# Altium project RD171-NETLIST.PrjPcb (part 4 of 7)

## Sheet 5.SchDoc
size 420 x 297 mm
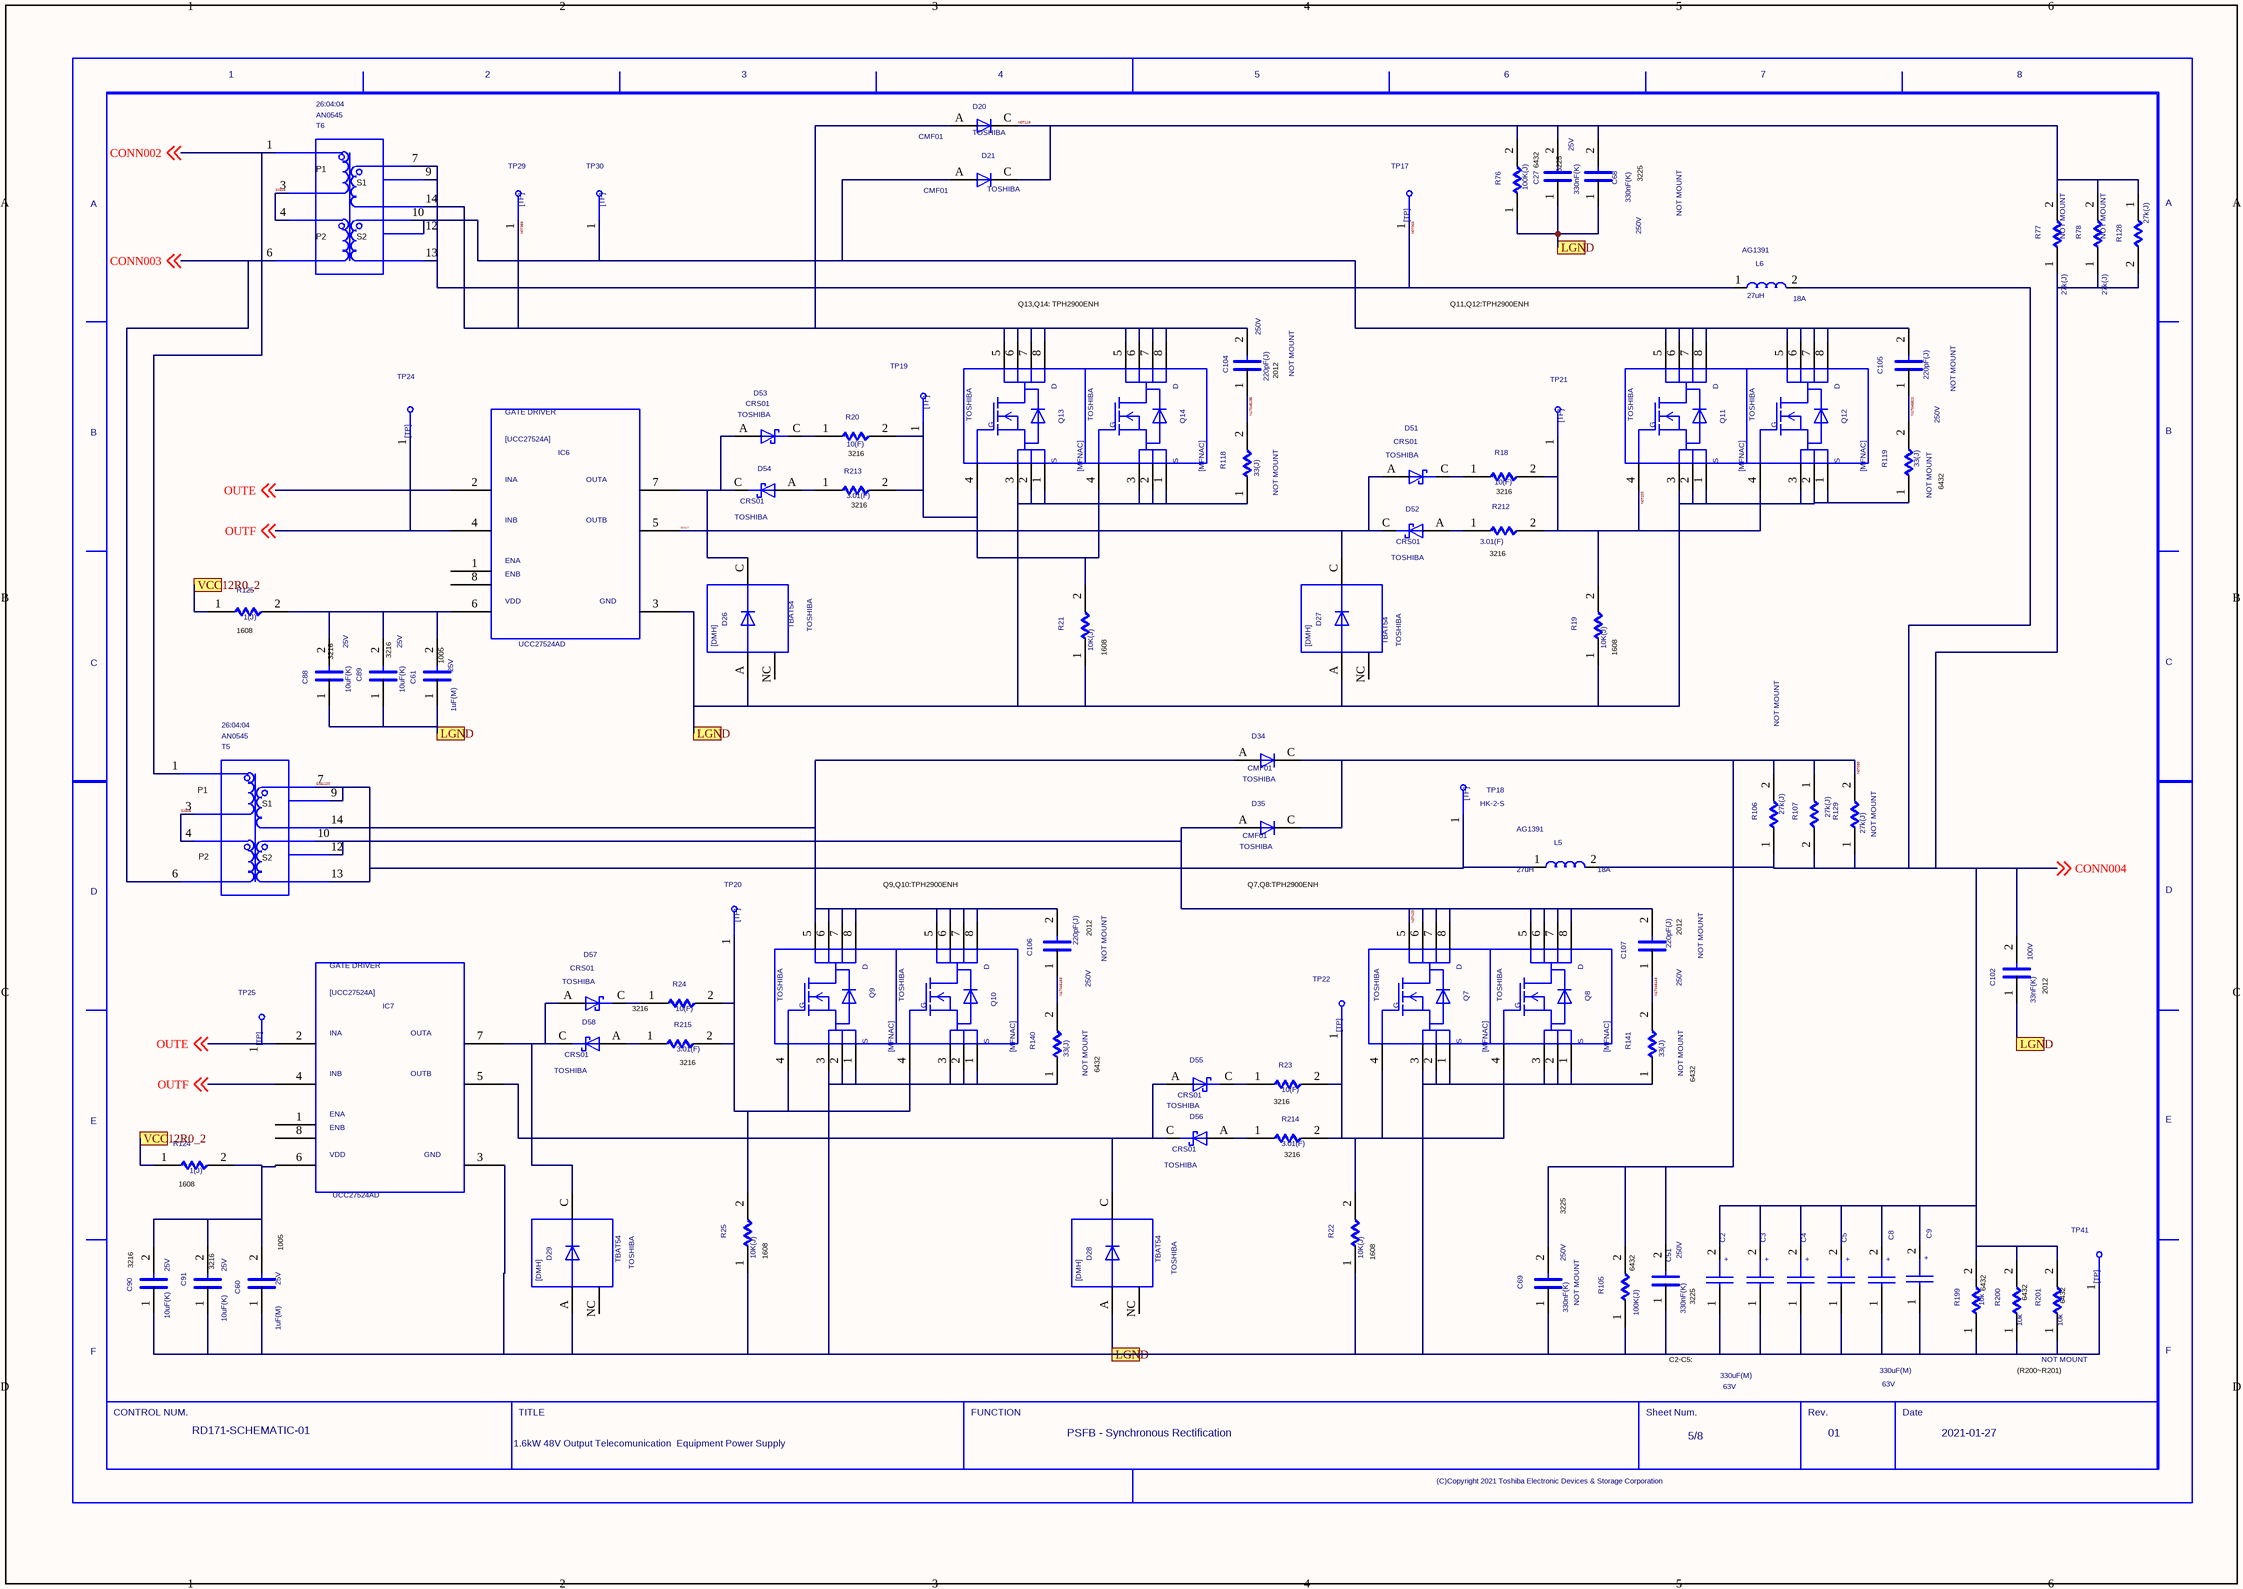
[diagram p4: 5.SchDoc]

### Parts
(Parts that share a designator on the sheet are numbered #1, #2 ... from top to bottom, then left to right.)
C2  VAL2: 63V  VAL1: 330uF(M)  [EKZN630ELL331MJ25S]  (hidden comment: 330uF)
C3  330uF  [EKZN630ELL331MJ25S]  (value not drawn)
C4  330uF  [EKZN630ELL331MJ25S]  (value not drawn)
C5  330uF  [EKZN630ELL331MJ25S]  (value not drawn)
C8  VAL2: 63V  VAL1: 330uF(M)  [EKZN630ELL331MJ25S]  (hidden comment: 330uF)
C9  330uF  [EKZN630ELL331MJ25S]  (value not drawn)
C27  VAL2: 25V  VAL1: 330nF(K)  [C3225X7T2E334K200AE]  (hidden comment: 330nF)
C51  VAL2: 250V  VAL1: 330nF(K)  [C3225X7T2E334K200AE]  (hidden comment: 330nF)
C60  VAL2: 25V  VAL1: 1uF(M)  (hidden comment: 1uF)
C61  VAL2: 25V  VAL1: 1uF(M)  (hidden comment: 1uF)
C68  MOUNT: NOT MOUNT  VAL2: 250V  VAL1: 330nF(K)  [C3225X7T2E334K200AE]  (hidden comment: 330nF)
C69  MOUNT: NOT MOUNT  VAL2: 250V  VAL1: 330nF(K)  [C3225X7T2E334K200AE]  (hidden comment: 330nF)
C88  VAL2: 25V  VAL1: 10uF(K)  (hidden comment: 10uF)
C89  VAL2: 25V  VAL1: 10uF(K)  (hidden comment: 10uF)
C90  VAL2: 25V  VAL1: 10uF(K)  (hidden comment: 10uF)
C91  VAL2: 25V  VAL1: 10uF(K)  (hidden comment: 10uF)
C102  VAL2: 100V  VAL1: 33nF(K)  [C2012C0G2A333J125AE]  (hidden comment: 33nF)
C104  MOUNT: NOT MOUNT  VAL2: 250V  VAL1: 220pF(J)  [GRM21A5C221J]  (hidden comment: 220pF)
C105  MOUNT: NOT MOUNT  VAL2: 250V  VAL1: 220pF(J)  [GRM21A5C221J]  (hidden comment: 220pF)
C106  MOUNT: NOT MOUNT  VAL2: 250V  VAL1: 220pF(J)  [GRM21A5C221J]  (hidden comment: 220pF)
C107  MOUNT: NOT MOUNT  VAL2: 250V  VAL1: 220pF(J)  [GRM21A5C221J]  (hidden comment: 220pF)
D20  USERCOMPTEXT3: TOSHIBA  [CMF01]  (hidden comment: D20)
D21  USERCOMPTEXT3: TOSHIBA  [CMF01]  (hidden comment: D21)
D26  USERCOMPTEXT3: TOSHIBA  [TBAT54]  (hidden comment: D26)
D27  USERCOMPTEXT3: TOSHIBA  [TBAT54]  (hidden comment: D27)
D28  USERCOMPTEXT3: TOSHIBA  [TBAT54]  (hidden comment: D28)
D29  USERCOMPTEXT3: TOSHIBA  [TBAT54]  (hidden comment: D29)
D34  USERCOMPTEXT3: TOSHIBA  [CMF01]  (hidden comment: D34)
D35  USERCOMPTEXT3: TOSHIBA  [CMF01]  (hidden comment: D35)
D51  USERCOMPTEXT3: TOSHIBA  [CRS01]  (hidden comment: D51)
D52  USERCOMPTEXT3: TOSHIBA  [CRS01]  (hidden comment: D52)
D53  USERCOMPTEXT3: TOSHIBA  [CRS01]  (hidden comment: D53)
D54  USERCOMPTEXT3: TOSHIBA  [CRS01]  (hidden comment: D54)
D55  USERCOMPTEXT3: TOSHIBA  [CRS01]  (hidden comment: D55)
D56  USERCOMPTEXT3: TOSHIBA  [CRS01]  (hidden comment: D56)
D57  USERCOMPTEXT3: TOSHIBA  [CRS01]  (hidden comment: D57)
D58  USERCOMPTEXT3: TOSHIBA  [CRS01]  (hidden comment: D58)
IC6  IC6  [UCC27524AD]  (value not drawn)
IC7  IC7  [UCC27524AD]  (value not drawn)
L5  VAL3: AG1391  VAL2: 18A  [AG-1391]  (hidden comment: 27uH)
L6  VAL3: AG1391  VAL2: 18A  [AG-1391]  (hidden comment: 27uH)
Q7  USERCOMPTEXT3: TOSHIBA  [TPH2900ENH]  (hidden comment: Q7)
Q8  USERCOMPTEXT3: TOSHIBA  [TPH2900ENH]  (hidden comment: Q8)
Q9  USERCOMPTEXT3: TOSHIBA  [TPH2900ENH]  (hidden comment: Q9)
Q10  USERCOMPTEXT3: TOSHIBA  [TPH2900ENH]  (hidden comment: Q10)
Q11  USERCOMPTEXT3: TOSHIBA  [TPH2900ENH]  (hidden comment: Q11)
Q12  USERCOMPTEXT3: TOSHIBA  [TPH2900ENH]  (hidden comment: Q12)
Q13  USERCOMPTEXT3: TOSHIBA  [TPH2900ENH]  (hidden comment: Q13)
Q14  USERCOMPTEXT3: TOSHIBA  [TPH2900ENH]  (hidden comment: Q14)
R18  VAL1: 10(F)  (hidden comment: 10)
R19  VAL1: 10K(J)  (hidden comment: 10k)
R20  VAL1: 10(F)  (hidden comment: 10)
R21  VAL1: 10K(J)  (hidden comment: 10k)
R22  VAL1: 10K(J)  (hidden comment: 10k)
R23  VAL1: 10(F)  (hidden comment: 10)
R24  VAL1: 10(F)  (hidden comment: 10)
R25  VAL1: 10K(J)  (hidden comment: 10k)
R76  VAL1: 100K(J)  [RK73B3ATTE104J]  (hidden comment: 100k)
R77  VAL2: NOT MOUNT  VAL1: 27k(J)  [MOS3CT631R273J]  (hidden comment: R)
R78  VAL2: NOT MOUNT  VAL1: 27k(J)  [MOS3CT631R273J]  (hidden comment: 27k)
R105  VAL1: 100K(J)  [RK73B3ATTE104J]  (hidden comment: 100k)
R106  VAL2: NOT MOUNT  VAL1: 27k(J)  [MOS3CT631R273J]  (hidden comment: 27k)
R107  VAL1: 27k(J)  [MOS3CT631R273J]  (hidden comment: 27k)
R118  VAL1: 33(J)  MOUNT: NOT MOUNT  [RK73B3ATTE330J]  (hidden comment: 33)
R119  VAL1: 33(J)  MOUNT: NOT MOUNT  [RK73B3ATTE330J]  (hidden comment: 33)
R124  VAL1: 1(J)  (hidden comment: 1)
R125  VAL1: 1(J)  (hidden comment: 1)
R128  VAL1: 27k(J)  [MOS3CT631R273J]  (hidden comment: 27k)
R129  VAL2: NOT MOUNT  VAL1: 27k(J)  [MOS3CT631R273J]  (hidden comment: 27k)
R140  VAL1: 33(J)  MOUNT: NOT MOUNT  [RK73B3ATTE330J]  (hidden comment: 33)
R141  VAL1: 33(J)  MOUNT: NOT MOUNT  [RK73B3ATTE330J]  (hidden comment: 33)
R199  10k  [RK73B3ATTE104J]
R200  NOTMOUNT: NOT MOUNT  [RK73B3ATTE104J]  (hidden comment: 10k)
R201  10k  [RK73B3ATTE104J]
R212  VAL1: 3.01(F)  (hidden comment: 3.01)
R213  VAL1: 3.01(F)  (hidden comment: 3.01)
R214  VAL1: 3.01(F)  (hidden comment: 3.01)
R215  VAL1: 3.01(F)  (hidden comment: 3.01)
T5  VAL1: 26:04:04  VAL3: AN0545  (hidden comment: T3_12V67A)
T6  VAL1: 26:04:04  VAL3: AN0545  (hidden comment: T3_12V67A)
TP17  TP17  [HK-2-S]  (value not drawn)
TP18  TP18  [HK-2-S]  (value not drawn)
TP19  TP19  [HK-2-S]  (value not drawn)
TP20  TP20  [HK-2-S]  (value not drawn)
TP21  TP21  [HK-2-S]  (value not drawn)
TP22  TP22  [HK-2-S]  (value not drawn)
TP24  TP24  [HK-2-S]  (value not drawn)
TP25  TP25  [HK-2-S]  (value not drawn)
TP29  TP29  [HK-2-S]  (value not drawn)
TP30  TP30  [HK-2-S]  (value not drawn)
TP41  TP41  [LC-22-S-BLACK]  (value not drawn)
U?#5  DATE: 2021-01-27  REVISION: 01  SHEETNUMBER: 5/8  FUNCTION: PSFB - Synchronous Rectification  TITLE: 1.6kW 48V Output Telecomunication / Equipment Power Supply  DRAWINGNUMBER: RD171-SCHEMATIC-01  (hidden comment: WAKU_DEF100)

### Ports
LGND, VCC12R0_2

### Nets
CONN002: T5.1 T6.1 ; off-sheet CONN002
CONN003: T5.6 T6.6 ; off-sheet CONN003
CONN004: C2.2 C3.2 C4.2 C5.2 C8.2 C9.2 C102.2 L5.2 L6.2 R77.1 R78.1 R106.1 R107.2 R128.2 R129.1 R199.2 R200.2 R201.2 ; off-sheet CONN004
LGND: C2.1 C3.1 C4.1 C5.1 C8.1 C9.1 C27.1 C51.1 C60.1 C61.1 C68.1 C69.1 C88.1 C89.1 C90.1 C91.1 C102.1 D26.A D27.A D28.A D29.A IC6.3 IC7.3 Q7.1 Q7.2 Q7.3 Q8.1 Q8.2 Q8.3 Q9.1 Q9.2 Q9.3 Q10.1 Q10.2 Q10.3 Q11.1 Q11.2 Q11.3 Q12.1 Q12.2 Q12.3 Q13.1 Q13.2 Q13.3 Q14.1 Q14.2 Q14.3 R19.1 R21.1 R22.1 R25.1 R76.1 R105.1 R118.1 R119.1 R140.1 R141.1 R199.1 R200.1 R201.1 TP41.1 ; port LGND
N07003: L6.1 T6.7 T6.9 T6.13 TP17.1
N07083: C51.2 C69.2 D34.C D35.C R105.2 R106.2 R107.1 R129.2
N07119: C27.2 C68.2 D20.C D21.C R76.2 R77.2 R78.2 R128.1
N07203: Q11.4 Q12.4 R18.2 R19.2 R212.2 TP21.1
N07369: C104.2 D20.A Q13.5 Q13.6 Q13.7 Q13.8 Q14.5 Q14.6 Q14.7 Q14.8 T6.14 TP29.1
N07429: C107.2 D35.A Q7.5 Q7.6 Q7.7 Q7.8 Q8.5 Q8.6 Q8.7 Q8.8 T5.10 T5.12
N17045135: C104.1 R118.2
N17045143: C107.1 R141.2
N17045153: C106.1 R140.2
N17045822: C105.1 R119.2
OUTE: IC6.2 IC7.2 TP25.1 ; off-sheet OUTE
OUTF: IC6.4 IC7.4 TP24.1 ; off-sheet OUTF
SIG14: T6.3 T6.4
SIG16: T5.3 T5.4
SIG115: C106.2 D34.A Q9.5 Q9.6 Q9.7 Q9.8 Q10.5 Q10.6 Q10.7 Q10.8 T5.14
SIG116: D29.C D57.A D58.C IC7.7
SIG117: D28.C D55.A D56.C IC7.5
SIG118: Q9.4 Q10.4 R24.2 R25.2 R215.2 TP20.1
SIG121: C60.2 C90.2 C91.2 IC7.6 R124.2
SIG124: C61.2 C88.2 C89.2 IC6.6 R125.2
SIG126: D26.C D53.A D54.C IC6.7
SIG127: D27.C D51.A D52.C IC6.5
SIG128: Q13.4 Q14.4 R20.2 R21.2 R213.2 TP19.1
SIG135: C105.2 D21.A Q11.5 Q11.6 Q11.7 Q11.8 Q12.5 Q12.6 Q12.7 Q12.8 T6.10 T6.12 TP30.1
SIG1120: L5.1 T5.7 T5.9 T5.13 TP18.1
SIGN336: D53.C R20.1
SIGN337: D54.A R213.1
SIGN338: D51.C R18.1
SIGN339: D52.A R212.1
SIGN341: D57.C R24.1
SIGN342: D58.A R215.1
SIGN343: Q7.4 Q8.4 R22.2 R23.2 R214.2 TP22.1
SIGN344: D55.C R23.1
SIGN345: D56.A R214.1
NetC809_2: R124.1 R125.1 ; port VCC12R0_2

Not connected (* = marked no-connect by the designer): D26 NC; D27 NC; D28 NC; D29 NC; IC6 1 8; IC7 1 8

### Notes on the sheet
- (near T6) P1
- (near T6) S1
- 6432
- (near C27) 3225
- (near C68) 3225
- (near T6) P2
- (near T6) S2
- Q13,Q14: TPH2900ENH
- Q11,Q12:TPH2900ENH
- (near C104) 2012
- (near R20) 3216
- (near R213) 3216
- (near R18) 3216
- (near R119) 6432
- (near R212) 3216
- (near R125) 1608
- (near C88) 3216
- (near C89) 3216
- (near C61) 1005
- (near R21) 1608
- (near R19) 1608
- (near T5) P1
- (near T5) P2
- (near T5) S2
- (near T5) S1
- Q9,Q10:TPH2900ENH
- (near C106) 2012
- Q7,Q8:TPH2900ENH
- (near C107) 2012
- (near C102) 2012
- 3216
- (near R215) 3216
- (near R140) 6432
- (near R23) 3216
- (near R141) 6432
- (near R124) 1608
- (near R214) 3216
- (near C90) 3216
- (near C91) 3216
- (near C60) 1005
- (near R25) 1608
- (near R22) 1608
- 3225
- (near R105) 6432
- (near R199) 6432
- (near R200) 6432
- (near R201) 6432
- C2-C5:
- (R200~R201)

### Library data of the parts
C2 = CP: PARTNAME: EKZN630ELL331MJ25S_CC; OUMEPARTTYPE: C; UPDATEUSER: t5459927; UPDATETIME: 16:40:04; SAVECOUNT: 1; SAVEAREA0: -1450,-153,20294,13055; ORIGINALSYMBOLORIGIN: (0,0); QUADMODEL: CON_56U; FUNCTION: CP_CP.Normal_package; NOMINALCAPACITA: 56u; RATEDVOLTAGE: 16; CDMASTERCADCELG: DC0341; MAKER: RUBYCON; SIZECODESMD: DIP; COMP: PRT_3; PMPRODUCTSTYPEG: SV1; FNLEADFREETHET1GT2GMCTH1: 0_2_N; CAPACITANCETOLE: M; OUMECLASSIFICATION: アルミ電解コンデンサ; CHIPSIZE: D10xL22; INSTANCENAME: INS5781
C3 = CP: PARTNAME: EKZN630ELL331MJ25S_CC; UPDATEUSER: t5459927; UPDATETIME: 16:40:04; SAVECOUNT: 1; SAVEAREA0: -1450,-153,20294,13055; ORIGINALSYMBOLORIGIN: (0,0); FUNCTION: CP_CP.Normal_package; NOMINALCAPACITA: 56u; RATEDVOLTAGE: 16; MAKER: RUBYCON; SIZECODESMD: DIP; COMP: PRT_3; PMPRODUCTSTYPEG: SV1; VAL3: 25ZLQ1500MEFC10X25; VAL2: 63V; CAPACITANCETOLE: M; VAL1: 330uF(M); CHIPSIZE: D10xL22; INSTANCENAME: INS5793
C4 = CP: PARTNAME: EKZN630ELL331MJ25S_CC; UPDATEUSER: t5459927; UPDATETIME: 16:40:04; SAVECOUNT: 1; SAVEAREA0: -1450,-153,20294,13055; ORIGINALSYMBOLORIGIN: (0,0); FUNCTION: CP_CP.Normal_package; NOMINALCAPACITA: 56u; RATEDVOLTAGE: 16; MAKER: RUBYCON; SIZECODESMD: DIP; COMP: PRT_3; PMPRODUCTSTYPEG: SV1; VAL3: 25ZLQ1500MEFC10X25; VAL2: 63V; CAPACITANCETOLE: M; VAL1: 330uF(M); CHIPSIZE: D10xL22; INSTANCENAME: INS5801
C5 = CP: PARTNAME: EKZN630ELL331MJ25S_CC; UPDATEUSER: t5459927; UPDATETIME: 16:40:04; SAVECOUNT: 1; SAVEAREA0: -1450,-153,20294,13055; ORIGINALSYMBOLORIGIN: (0,0); FUNCTION: CP_CP.Normal_package; NOMINALCAPACITA: 56u; RATEDVOLTAGE: 16; MAKER: RUBYCON; SIZECODESMD: DIP; COMP: PRT_3; PMPRODUCTSTYPEG: SV1; VAL3: 25ZLQ1500MEFC10X25; VAL2: 63V; CAPACITANCETOLE: M; VAL1: 330uF(M); CHIPSIZE: D10xL22; INSTANCENAME: INS5809
C8 = CP: PARTNAME: EKZN630ELL331MJ25S_CC; UPDATEUSER: t5459927; UPDATETIME: 16:40:04; SAVECOUNT: 1; SAVEAREA0: -1450,-153,20294,13055; ORIGINALSYMBOLORIGIN: (0,0); FUNCTION: CP_CP.Normal_package; NOMINALCAPACITA: 56u; RATEDVOLTAGE: 16; MAKER: RUBYCON; SIZECODESMD: DIP; COMP: PRT_3; PMPRODUCTSTYPEG: SV1; VAL3: EKZN630ELL331M; CAPACITANCETOLE: M; CHIPSIZE: D10xL22; INSTANCENAME: INS17034209
C9 = CP: PARTNAME: EKZN630ELL331MJ25S_CC; UPDATEUSER: t5459927; UPDATETIME: 16:40:04; SAVECOUNT: 1; SAVEAREA0: -1450,-153,20294,13055; ORIGINALSYMBOLORIGIN: (0,0); FUNCTION: CP_CP.Normal_package; NOMINALCAPACITA: 56u; RATEDVOLTAGE: 16; MAKER: RUBYCON; SIZECODESMD: DIP; COMP: PRT_3; PMPRODUCTSTYPEG: SV1; VAL3: EKZN630ELL331M; VAL2: 63V; CAPACITANCETOLE: M; VAL1: 330uF(M); CHIPSIZE: D10xL22; INSTANCENAME: INS17035630
C27 = C: PARTNAME: Chip3225_GS_1; ORIGINALSYMBOLORIGIN: (0,0); TIME: 16:40:04; UPDATEUSER: t5459927; SAVECOUNT: 1; QUADMODEL: CON_220N; FUNCTION: C_C.Normal_package; NOMINALCAPACITA: 220n; RATEDVOLTAGE: 16; CDMASTERCADCELG: KC0005; MAKER: TDK; TEMPCHARACTERI2: B; SIZECODESMD: 1005; OUMEMAKER: TDK ＴＤＫ; COMP: PRT_52; ADSMODELNAME: s_C1005JB1C224KT; FNLEADFREETHET1GT2GMCTH1: N_N_N; VAL3: C1005X5R1E224K050BC; CAPACITANCETOLE: K; OUMECLASSIFICATION: セラミックコンデンサ; OUMEMAKERKATAMEI: C1005JB1C224KT; INSTANCENAME: INS6475
C51 = C: PARTNAME: Chip3225_GS_1; ORIGINALSYMBOLORIGIN: (0,0); TIME: 16:40:04; UPDATEUSER: t5459927; SAVECOUNT: 1; QUADMODEL: CON_220N; FUNCTION: C_C.Normal_package; NOMINALCAPACITA: 220n; RATEDVOLTAGE: 16; CDMASTERCADCELG: KC0005; MAKER: TDK; TEMPCHARACTERI2: B; SIZECODESMD: 3225; OUMEMAKER: TDK ＴＤＫ; COMP: PRT_52; ADSMODELNAME: s_C1005JB1C224KT; FNLEADFREETHET1GT2GMCTH1: N_N_N; CAPACITANCETOLE: K; OUMECLASSIFICATION: セラミックコンデンサ; CHIPSIZE: 1005; INSTANCENAME: INS17062697
C60 = C: PARTNAME: Chip1005_GS_2; ORIGINALSYMBOLORIGIN: (0,0); TIME: 16:40:04; UPDATEUSER: t5459927; SAVECOUNT: 1; QUADMODEL: CON_1U; FUNCTION: C_C.Normal_package; NOMINALCAPACITA: 1u; RATEDVOLTAGE: 25; CDMASTERCADCELG: KC0005; MAKER: TDK; TEMPCHARACTERI2: B; SIZECODESMD: 1005; OUMEMAKER: MRT 村田製作所; COMP: PRT_52; ADSMODELNAME: s_GRM155B31E105KA12D; PMPRODUCTSTYPEG: HD1; FNLEADFREETHET1GT2GMCTH1: 3_0_N; VAL3: C1005X5R1E105M050BC; CAPACITANCETOLE: K; OUMECLASSIFICATION: セラミックコンデンサ; OUMEMAKERKATAMEI: GRM155B31E105KA12D; INSTANCENAME: INS6615
C61 = C: PARTNAME: Chip1005_GS_2; ORIGINALSYMBOLORIGIN: (0,0); TIME: 16:40:04; UPDATEUSER: t5459927; SAVECOUNT: 1; QUADMODEL: CON_1U; FUNCTION: C_C.Normal_package; NOMINALCAPACITA: 1u; RATEDVOLTAGE: 25; CDMASTERCADCELG: KC0005; MAKER: TDK; TEMPCHARACTERI2: B; SIZECODESMD: 1005; OUMEMAKER: MRT 村田製作所; COMP: PRT_52; ADSMODELNAME: s_GRM155B31E105KA12D; PMPRODUCTSTYPEG: HD1; FNLEADFREETHET1GT2GMCTH1: 3_0_N; VAL3: C1005X5R1E105M050BC; CAPACITANCETOLE: K; OUMECLASSIFICATION: セラミックコンデンサ; OUMEMAKERKATAMEI: GRM155B31E105KA12D; INSTANCENAME: INS6565
C68 = C: PARTNAME: Chip3225_GS_1; ORIGINALSYMBOLORIGIN: (0,0); TIME: 16:40:04; UPDATEUSER: t5459927; SAVECOUNT: 1; NOTMOUNT: NOT MOUNT; QUADMODEL: CON_220N; FUNCTION: C_C.Normal_package; NOMINALCAPACITA: 220n; RATEDVOLTAGE: 16; CDMASTERCADCELG: KC0005; MAKER: TDK; TEMPCHARACTERI2: B; SIZECODESMD: 3225; OUMEMAKER: TDK ＴＤＫ; COMP: PRT_52; ADSMODELNAME: s_C1005JB1C224KT; FNLEADFREETHET1GT2GMCTH1: N_N_N; CAPACITANCETOLE: K; OUMECLASSIFICATION: セラミックコンデンサ; CHIPSIZE: 1005; INSTANCENAME: INS17036811
C69 = C: PARTNAME: Chip3225_GS_1; ORIGINALSYMBOLORIGIN: (0,0); TIME: 16:40:04; UPDATEUSER: t5459927; SAVECOUNT: 1; NOTMOUNT: NOT MOUNT; QUADMODEL: CON_220N; FUNCTION: C_C.Normal_package; NOMINALCAPACITA: 220n; RATEDVOLTAGE: 16; CDMASTERCADCELG: KC0005; MAKER: TDK; TEMPCHARACTERI2: B; SIZECODESMD: 3225; OUMEMAKER: TDK ＴＤＫ; COMP: PRT_52; ADSMODELNAME: s_C1005JB1C224KT; FNLEADFREETHET1GT2GMCTH1: N_N_N; CAPACITANCETOLE: K; OUMECLASSIFICATION: セラミックコンデンサ; CHIPSIZE: 1005; INSTANCENAME: INS17039422
C88 = C: PARTNAME: Chip3216_GS_1; ORIGINALSYMBOLORIGIN: (0,0); TIME: 16:40:04; UPDATEUSER: t5459927; SAVECOUNT: 1; QUADMODEL: CON_10U; FUNCTION: C_C.Normal_package; NOMINALCAPACITA: 10u; RATEDVOLTAGE: 25; CDMASTERCADCELG: KC0014; MAKER: TAIYO YUDEN; SIZECODESMD: 3216; OUMEMAKER: TYD 太陽誘電; COMP: PRT_46; ADSMODELNAME: s_TMK316LD106KL_T; FNLEADFREETHET1GT2GMCTH1: N_N_N; VAL3: TMK316BJ106KL-T; CAPACITANCETOLE: K; OUMECLASSIFICATION: セラミックコンデンサ; OUMEMAKERKATAMEI: TMK316LD106KL-T; INSTANCENAME: INS6555
C89 = C: PARTNAME: Chip3216_GS_1; ORIGINALSYMBOLORIGIN: (0,0); TIME: 16:40:04; UPDATEUSER: t5459927; SAVECOUNT: 1; QUADMODEL: CON_10U; FUNCTION: C_C.Normal_package; NOMINALCAPACITA: 10u; RATEDVOLTAGE: 25; CDMASTERCADCELG: KC0014; MAKER: TAIYO YUDEN; SIZECODESMD: 3216; OUMEMAKER: TYD 太陽誘電; COMP: PRT_46; ADSMODELNAME: s_TMK316LD106KL_T; FNLEADFREETHET1GT2GMCTH1: N_N_N; VAL3: TMK316BJ106KL-T; CAPACITANCETOLE: K; OUMECLASSIFICATION: セラミックコンデンサ; OUMEMAKERKATAMEI: TMK316LD106KL-T; INSTANCENAME: INS6545
C90 = C: PARTNAME: Chip3216_GS_1; ORIGINALSYMBOLORIGIN: (0,0); TIME: 16:40:04; UPDATEUSER: t5459927; SAVECOUNT: 1; QUADMODEL: CON_10U; FUNCTION: C_C.Normal_package; NOMINALCAPACITA: 10u; RATEDVOLTAGE: 25; CDMASTERCADCELG: KC0014; MAKER: TAIYO YUDEN; SIZECODESMD: 3216; OUMEMAKER: TYD 太陽誘電; COMP: PRT_46; ADSMODELNAME: s_TMK316LD106KL_T; FNLEADFREETHET1GT2GMCTH1: N_N_N; VAL3: TMK316BJ106KL-T; CAPACITANCETOLE: K; OUMECLASSIFICATION: セラミックコンデンサ; OUMEMAKERKATAMEI: TMK316LD106KL-T; INSTANCENAME: INS6595
C91 = C: PARTNAME: Chip3216_GS_1; ORIGINALSYMBOLORIGIN: (0,0); TIME: 16:40:04; UPDATEUSER: t5459927; SAVECOUNT: 1; QUADMODEL: CON_10U; FUNCTION: C_C.Normal_package; NOMINALCAPACITA: 10u; RATEDVOLTAGE: 25; CDMASTERCADCELG: KC0014; MAKER: TAIYO YUDEN; SIZECODESMD: 3216; OUMEMAKER: TYD 太陽誘電; COMP: PRT_46; ADSMODELNAME: s_TMK316LD106KL_T; FNLEADFREETHET1GT2GMCTH1: N_N_N; VAL3: TMK316BJ106KL-T; CAPACITANCETOLE: K; OUMECLASSIFICATION: セラミックコンデンサ; OUMEMAKERKATAMEI: TMK316LD106KL-T; INSTANCENAME: INS6605
C102 = C: PARTNAME: Chip2012_GS_1; ORIGINALSYMBOLORIGIN: (0,0); TIME: 16:40:04; UPDATEUSER: t5459927; SAVECOUNT: 1; QUADMODEL: CON_100N; FUNCTION: C_C.Normal_package; NOMINALCAPACITA: 100n; RATEDVOLTAGE: 25; CDMASTERCADCELG: KC0005; MAKER: TDK; SIZECODESMD: 1005; OUMEMAKER: MRT 村田製作所; COMP: PRT_52; ADSMODELNAME: s_GRM155R71E104KE14D; FNLEADFREETHET1GT2GMCTH1: N_N_N; CAPACITANCETOLE: K; OUMECLASSIFICATION: セラミックコンデンサ; OUMEMAKERKATAMEI: GRM155R71E104KE14D; INSTANCENAME: INS6675
C104 = C: PARTNAME: Chip2012_GS_1; ORIGINALSYMBOLORIGIN: (0,0); TIME: 16:40:04; UPDATEUSER: t5459927; SAVECOUNT: 1; NOTMOUNT: NOT MOUNT; QUADMODEL: CON_100N; FUNCTION: C_C.Normal_package; NOMINALCAPACITA: 100n; RATEDVOLTAGE: 250; CDMASTERCADCELG: KC0005; MAKER: MURATA; SIZECODESMD: 2012; OUMEMAKER: MRT 村田製作所; COMP: PRT_52; ADSMODELNAME: s_GRM155R71E104KE14D; FNLEADFREETHET1GT2GMCTH1: N_N_N; VAL3: GRM21A5C2E221J; CAPACITANCETOLE: K; OUMECLASSIFICATION: セラミックコンデンサ; OUMEMAKERKATAMEI: GRM21A5C2E221JW01D; INSTANCENAME: INS17040886
C105 = C: PARTNAME: Chip2012_GS_1; ORIGINALSYMBOLORIGIN: (0,0); TIME: 16:40:04; UPDATEUSER: t5459927; SAVECOUNT: 1; NOTMOUNT: NOT MOUNT; QUADMODEL: CON_100N; FUNCTION: C_C.Normal_package; NOMINALCAPACITA: 100n; RATEDVOLTAGE: 250; CDMASTERCADCELG: KC0005; MAKER: MURATA; SIZECODESMD: 2012; OUMEMAKER: MRT 村田製作所; COMP: PRT_52; ADSMODELNAME: s_GRM155R71E104KE14D; FNLEADFREETHET1GT2GMCTH1: N_N_N; VAL3: GRM21A5C2E221J; CAPACITANCETOLE: K; OUMECLASSIFICATION: セラミックコンデンサ; OUMEMAKERKATAMEI: GRM21A5C2E221JW01D; INSTANCENAME: INS17040900
C106 = C: PARTNAME: Chip2012_GS_1; ORIGINALSYMBOLORIGIN: (0,0); TIME: 16:40:04; UPDATEUSER: t5459927; SAVECOUNT: 1; NOTMOUNT: NOT MOUNT; QUADMODEL: CON_100N; FUNCTION: C_C.Normal_package; NOMINALCAPACITA: 100n; RATEDVOLTAGE: 250; CDMASTERCADCELG: KC0005; MAKER: MURATA; SIZECODESMD: 2012; OUMEMAKER: MRT 村田製作所; COMP: PRT_52; ADSMODELNAME: s_GRM155R71E104KE14D; FNLEADFREETHET1GT2GMCTH1: N_N_N; VAL3: GRM21A5C2E221J; CAPACITANCETOLE: K; OUMECLASSIFICATION: セラミックコンデンサ; OUMEMAKERKATAMEI: GRM21A5C2E221JW01D; INSTANCENAME: INS17040913
C107 = C: PARTNAME: Chip2012_GS_1; ORIGINALSYMBOLORIGIN: (0,0); TIME: 16:40:04; UPDATEUSER: t5459927; SAVECOUNT: 1; NOTMOUNT: NOT MOUNT; QUADMODEL: CON_100N; FUNCTION: C_C.Normal_package; NOMINALCAPACITA: 100n; RATEDVOLTAGE: 250; CDMASTERCADCELG: KC0005; MAKER: MURATA; SIZECODESMD: 2012; OUMEMAKER: MRT 村田製作所; COMP: PRT_52; ADSMODELNAME: s_GRM155R71E104KE14D; FNLEADFREETHET1GT2GMCTH1: N_N_N; VAL3: GRM21A5C2E221J; CAPACITANCETOLE: K; OUMECLASSIFICATION: セラミックコンデンサ; OUMEMAKERKATAMEI: GRM21A5C2E221JW01D; INSTANCENAME: INS17040926
D20 = D: PARTNAME: CMF01_TS_B; UPDATEUSER: t5459927; UPDATETIME: 16:40:05; SAVECOUNT: 1; SAVEAREA0: -225,-91,12804,7836; ORIGINALSYMBOLORIGIN: (0,0); FUNCTION: D_D.Normal_package; CDMASTERCADCELG: KD0125; FORWARDVOLTAGEM: 0; MAXAVERAGEFORWA: 4; OUMEMAKER: ONS オンセミコンダクター; MOUNTINGFORMSMD: SMD; COMP: PRT_14; REVERSECURRENT: 250u; ADSMODELNAME: s_MURS340T3G@@; PMPRODUCTSTYPEG: HEV; MAXREPETITIVEPE: 400; FNLEADFREETHET1GT2GMCTH1: N_N_N; OUMECLASSIFICATION: 一般整流素子; OUMEMAKERKATAMEI: MURS340T3G@@; PEAKFORWARDVOLT: 1.28; INSTANCENAME: INS5897
D21 = D: PARTNAME: CMF01_TS_B; UPDATEUSER: t5459927; UPDATETIME: 16:40:05; SAVECOUNT: 1; SAVEAREA0: -225,-91,12804,7836; ORIGINALSYMBOLORIGIN: (0,0); FUNCTION: D_D.Normal_package; CDMASTERCADCELG: KD0125; FORWARDVOLTAGEM: 0; MAXAVERAGEFORWA: 4; OUMEMAKER: ONS オンセミコンダクター; MOUNTINGFORMSMD: SMD; COMP: PRT_14; REVERSECURRENT: 250u; ADSMODELNAME: s_MURS340T3G@@; PMPRODUCTSTYPEG: HEV; MAXREPETITIVEPE: 400; FNLEADFREETHET1GT2GMCTH1: N_N_N; OUMECLASSIFICATION: 一般整流素子; OUMEMAKERKATAMEI: MURS340T3G@@; PEAKFORWARDVOLT: 1.28; INSTANCENAME: INS5909
D26 = DMH: PARTNAME: TBAT54_TS_B; UPDATEUSER: t5459927; UPDATETIME: 16:40:05; SAVECOUNT: 1; SAVEAREA0: -4931,-287,27399,20979; ORIGINALSYMBOLORIGIN: (0,0); COMPONENTNAME: DMH_DMH.Normal_package; COMP: PRT_25; INSTANCENAME: INS5825
D27 = DMH: PARTNAME: TBAT54_TS_B; UPDATEUSER: t5459927; UPDATETIME: 16:40:05; SAVECOUNT: 1; SAVEAREA0: -4931,-287,27399,20979; ORIGINALSYMBOLORIGIN: (0,0); COMPONENTNAME: DMH_DMH.Normal_package; COMP: PRT_25; INSTANCENAME: INS5883
D28 = DMH: PARTNAME: TBAT54_TS_B; UPDATEUSER: t5459927; UPDATETIME: 16:40:05; SAVECOUNT: 1; SAVEAREA0: -4931,-287,27399,20979; ORIGINALSYMBOLORIGIN: (0,0); COMPONENTNAME: DMH_DMH.Normal_package; COMP: PRT_25; INSTANCENAME: INS5767
D29 = DMH: PARTNAME: TBAT54_TS_B; UPDATEUSER: t5459927; UPDATETIME: 16:40:05; SAVECOUNT: 1; SAVEAREA0: -4931,-287,27399,20979; ORIGINALSYMBOLORIGIN: (0,0); COMPONENTNAME: DMH_DMH.Normal_package; COMP: PRT_25; INSTANCENAME: INS5753
D34 = D: PARTNAME: CMF01_TS_B; UPDATEUSER: t5459927; UPDATETIME: 16:40:05; SAVECOUNT: 1; SAVEAREA0: -225,-91,12804,7836; ORIGINALSYMBOLORIGIN: (0,0); FUNCTION: D_D.Normal_package; CDMASTERCADCELG: KD0125; FORWARDVOLTAGEM: 0; MAXAVERAGEFORWA: 4; OUMEMAKER: ONS オンセミコンダクター; MOUNTINGFORMSMD: SMD; COMP: PRT_14; REVERSECURRENT: 250u; ADSMODELNAME: s_MURS340T3G@@; PMPRODUCTSTYPEG: HEV; MAXREPETITIVEPE: 400; FNLEADFREETHET1GT2GMCTH1: N_N_N; OUMECLASSIFICATION: 一般整流素子; OUMEMAKERKATAMEI: MURS340T3G@@; PEAKFORWARDVOLT: 1.28; INSTANCENAME: INS5675
D35 = D: PARTNAME: CMF01_TS_B; UPDATEUSER: t5459927; UPDATETIME: 16:40:05; SAVECOUNT: 1; SAVEAREA0: -225,-91,12804,7836; ORIGINALSYMBOLORIGIN: (0,0); FUNCTION: D_D.Normal_package; CDMASTERCADCELG: KD0125; FORWARDVOLTAGEM: 0; MAXAVERAGEFORWA: 4; OUMEMAKER: ONS オンセミコンダクター; MOUNTINGFORMSMD: SMD; COMP: PRT_14; REVERSECURRENT: 250u; ADSMODELNAME: s_MURS340T3G@@; PMPRODUCTSTYPEG: HEV; MAXREPETITIVEPE: 400; FNLEADFREETHET1GT2GMCTH1: N_N_N; OUMECLASSIFICATION: 一般整流素子; OUMEMAKERKATAMEI: MURS340T3G@@; PEAKFORWARDVOLT: 1.28; INSTANCENAME: INS5663
D51 = SBD: PARTNAME: CRS01_TS_B; UPDATEUSER: t5459927; UPDATETIME: 16:40:05; SAVECOUNT: 1; SAVEAREA0: -4630,-153,17114,13055; ORIGINALSYMBOLORIGIN: (0,0); COMPONENTNAME: SBD_SBD.Normal_package; COMP: PRT_11; INSTANCENAME: INS6339
D52 = SBD: PARTNAME: CRS01_TS_B; UPDATEUSER: t5459927; UPDATETIME: 16:40:05; SAVECOUNT: 1; SAVEAREA0: -4630,-153,17114,13055; ORIGINALSYMBOLORIGIN: (0,0); COMPONENTNAME: SBD_SBD.Normal_package; COMP: PRT_11; INSTANCENAME: INS6329
D53 = SBD: PARTNAME: CRS01_TS_B; UPDATEUSER: t5459927; UPDATETIME: 16:40:05; SAVECOUNT: 1; SAVEAREA0: -4630,-153,17114,13055; ORIGINALSYMBOLORIGIN: (0,0); COMPONENTNAME: SBD_SBD.Normal_package; COMP: PRT_11; INSTANCENAME: INS6317
D54 = SBD: PARTNAME: CRS01_TS_B; UPDATEUSER: t5459927; UPDATETIME: 16:40:05; SAVECOUNT: 1; SAVEAREA0: -4630,-153,17114,13055; ORIGINALSYMBOLORIGIN: (0,0); COMPONENTNAME: SBD_SBD.Normal_package; COMP: PRT_11; INSTANCENAME: INS6307
D55 = SBD: PARTNAME: CRS01_TS_B; UPDATEUSER: t5459927; UPDATETIME: 16:40:05; SAVECOUNT: 1; SAVEAREA0: -4630,-153,17114,13055; ORIGINALSYMBOLORIGIN: (0,0); COMPONENTNAME: SBD_SBD.Normal_package; COMP: PRT_11; INSTANCENAME: INS6361
D56 = SBD: PARTNAME: CRS01_TS_B; UPDATEUSER: t5459927; UPDATETIME: 16:40:05; SAVECOUNT: 1; SAVEAREA0: -4630,-153,17114,13055; ORIGINALSYMBOLORIGIN: (0,0); COMPONENTNAME: SBD_SBD.Normal_package; COMP: PRT_11; INSTANCENAME: INS6351
D57 = SBD: PARTNAME: CRS01_TS_B; UPDATEUSER: t5459927; UPDATETIME: 16:40:05; SAVECOUNT: 1; SAVEAREA0: -4630,-153,17114,13055; ORIGINALSYMBOLORIGIN: (0,0); COMPONENTNAME: SBD_SBD.Normal_package; COMP: PRT_11; INSTANCENAME: INS6383
D58 = SBD: PARTNAME: CRS01_TS_B; UPDATEUSER: t5459927; UPDATETIME: 16:40:05; SAVECOUNT: 1; SAVEAREA0: -4630,-153,17114,13055; ORIGINALSYMBOLORIGIN: (0,0); COMPONENTNAME: SBD_SBD.Normal_package; COMP: PRT_11; INSTANCENAME: INS6373
IC6 = L27524: PARTNAME: UCC27524ADR_TI; UPDATEUSER: t5459927; UPDATETIME: 16:40:04; SAVECOUNT: 1; SAVEAREA0: -37147,-44052,63643,2408; ORIGINALSYMBOLORIGIN: (0,0); COMP: PRT_63; FUNCTION: L27524_L27524.Normal_package; MAKER: TEXAS; INSTANCENAME: INS5965
IC7 = L27524: PARTNAME: UCC27524ADR_TI; UPDATEUSER: t5459927; UPDATETIME: 16:40:04; SAVECOUNT: 1; SAVEAREA0: -37147,-44052,63643,2408; ORIGINALSYMBOLORIGIN: (0,0); COMP: PRT_63; FUNCTION: L27524_L27524.Normal_package; MAKER: TEXAS; INSTANCENAME: INS5987
L5 = L: PARTNAME: AG1391_GS; ORIGINALSYMBOLORIGIN: (0,0); TIME: 16:40:05; UPDATEUSER: t5459927; SAVECOUNT: 1; COMPONENTNAME: L_L.Normal_package; ADSMODELNAME: s_LPI_1R2D13; INDUCTANCEMIN: 0; MOUNTINGFORMSMD: SMD; MAKER: TOKYO SEIDEN; NOMINALINDUCTA2: X; NOMINALINDUCTA1: 1.2u; COMP: PRT_40; INSTANCENAME: INS6019
L6 = L: PARTNAME: AG1391_GS; ORIGINALSYMBOLORIGIN: (0,0); TIME: 16:40:05; UPDATEUSER: t5459927; SAVECOUNT: 1; COMPONENTNAME: L_L.Normal_package; ADSMODELNAME: s_LPI_1R2D13; INDUCTANCEMIN: 0; MOUNTINGFORMSMD: SMD; MAKER: TOKYO SEIDEN; NOMINALINDUCTA2: X; NOMINALINDUCTA1: 1.2u; COMP: PRT_40; INSTANCENAME: INS6033
Q7 = MFNAC: PARTNAME: TPH2900ENH_TS; UPDATEUSER: t5459927; UPDATETIME: 16:40:05; SAVECOUNT: 1; SAVEAREA0: -10143,-336,37609,28718; ORIGINALSYMBOLORIGIN: (0,0); COMPONENTNAME: MFNAC_MFNAC.Normal_package; COMP: PRT_67; INSTANCENAME: INS5731
Q8 = MFNAC: PARTNAME: TPH2900ENH_TS; UPDATEUSER: t5459927; UPDATETIME: 16:40:05; SAVECOUNT: 1; SAVEAREA0: -10143,-336,37609,28718; ORIGINALSYMBOLORIGIN: (0,0); COMPONENTNAME: MFNAC_MFNAC.Normal_package; COMP: PRT_67; INSTANCENAME: INS5709
Q9 = MFNAC: PARTNAME: TPH2900ENH_TS; UPDATEUSER: t5459927; UPDATETIME: 16:40:05; SAVECOUNT: 1; SAVEAREA0: -10143,-336,37609,28718; ORIGINALSYMBOLORIGIN: (0,0); COMPONENTNAME: MFNAC_MFNAC.Normal_package; COMP: PRT_67; INSTANCENAME: INS6201
Q10 = MFNAC: PARTNAME: TPH2900ENH_TS; UPDATEUSER: t5459927; UPDATETIME: 16:40:05; SAVECOUNT: 1; SAVEAREA0: -10143,-336,37609,28718; ORIGINALSYMBOLORIGIN: (0,0); COMPONENTNAME: MFNAC_MFNAC.Normal_package; COMP: PRT_67; INSTANCENAME: INS5641
Q11 = MFNAC: PARTNAME: TPH2900ENH_TS; UPDATEUSER: t5459927; UPDATETIME: 16:40:05; SAVECOUNT: 1; SAVEAREA0: -10143,-336,37609,28718; ORIGINALSYMBOLORIGIN: (0,0); COMPONENTNAME: MFNAC_MFNAC.Normal_package; COMP: PRT_67; INSTANCENAME: INS5943
Q12 = MFNAC: PARTNAME: TPH2900ENH_TS; UPDATEUSER: t5459927; UPDATETIME: 16:40:05; SAVECOUNT: 1; SAVEAREA0: -10143,-336,37609,28718; ORIGINALSYMBOLORIGIN: (0,0); COMPONENTNAME: MFNAC_MFNAC.Normal_package; COMP: PRT_67; INSTANCENAME: INS5921
Q13 = MFNAC: PARTNAME: TPH2900ENH_TS; UPDATEUSER: t5459927; UPDATETIME: 16:40:05; SAVECOUNT: 1; SAVEAREA0: -10143,-336,37609,28718; ORIGINALSYMBOLORIGIN: (0,0); COMPONENTNAME: MFNAC_MFNAC.Normal_package; COMP: PRT_67; INSTANCENAME: INS6179
Q14 = MFNAC: PARTNAME: TPH2900ENH_TS; UPDATEUSER: t5459927; UPDATETIME: 16:40:05; SAVECOUNT: 1; SAVEAREA0: -10143,-336,37609,28718; ORIGINALSYMBOLORIGIN: (0,0); COMPONENTNAME: MFNAC_MFNAC.Normal_package; COMP: PRT_67; INSTANCENAME: INS5861
R18 = R: PARTNAME: Chip3216_GS_1; ORIGINALSYMBOLORIGIN: (0,0); TIME: 16:40:04; UPDATEUSER: t5459927; SAVECOUNT: 1; QUADMODEL: RES_3.3; FUNCTION: R_R.Normal_package; CDMASTERCADCELG: KC0014; MAKER: VISHAY; RESISTANCETOLER: J; SIZECODESMD: 3216; OUMEMAKER: NAE パナソニックエレクトロニックデバイス; POWERRATING: 250m; MOUNTINGFORMSMD: SMD; NOMINALRESISTAN: 3.3; COMP: PRT_5; ADSMODELNAME: s_ERJ8GEYJ3R3V; FNLEADFREETHET1GT2GMCTH1: N_N_N; VAL3: CRCW12063R01FKEAHP; VAL2: 500mW,±1%; OUMECLASSIFICATION: 表面実装用固定抵抗器; OUMEMAKERKATAMEI: ERJ8GEYJ3R3V; INSTANCENAME: INS6505
R19 = R: PARTNAME: Chip1608_GS_1; ORIGINALSYMBOLORIGIN: (0,0); TIME: 16:40:04; UPDATEUSER: t5459927; SAVECOUNT: 1; QUADMODEL: RES_10K; FUNCTION: R_R.Normal_package; CDMASTERCADCELG: KC0133; MAKER: KOA; RESISTANCETOLER: J; SIZECODESMD: 1608; OUMEMAKER: KOA コーア; POWERRATING: 100m; MOUNTINGFORMSMD: SMD; COMP: PRT_8; ADSMODELNAME: s_RK73B1JTTD103J@@; FNLEADFREETHET1GT2GMCTH1: N_N_N; VAL3: RK73B1JTTD103J; VAL2: 100mW,±5%; OUMECLASSIFICATION: 表面実装用固定抵抗器; OUMEMAKERKATAMEI: RK73B1JTTD103J@@; INSTANCENAME: INS6525
R20 = R: PARTNAME: Chip3216_GS_1; ORIGINALSYMBOLORIGIN: (0,0); TIME: 16:40:04; UPDATEUSER: t5459927; SAVECOUNT: 1; QUADMODEL: RES_3.3; FUNCTION: R_R.Normal_package; CDMASTERCADCELG: KC0014; MAKER: VISHAY; RESISTANCETOLER: J; SIZECODESMD: 3216; OUMEMAKER: NAE パナソニックエレクトロニックデバイス; POWERRATING: 250m; MOUNTINGFORMSMD: SMD; NOMINALRESISTAN: 3.3; COMP: PRT_5; ADSMODELNAME: s_ERJ8GEYJ3R3V; FNLEADFREETHET1GT2GMCTH1: N_N_N; VAL3: CRCW12063R01FKEAHP; VAL2: 500mW,±1%; OUMECLASSIFICATION: 表面実装用固定抵抗器; OUMEMAKERKATAMEI: ERJ8GEYJ3R3V; INSTANCENAME: INS6495
R21 = R: PARTNAME: Chip1608_GS_1; ORIGINALSYMBOLORIGIN: (0,0); TIME: 16:40:04; UPDATEUSER: t5459927; SAVECOUNT: 1; QUADMODEL: RES_10K; FUNCTION: R_R.Normal_package; CDMASTERCADCELG: KC0133; MAKER: KOA; RESISTANCETOLER: J; SIZECODESMD: 1608; OUMEMAKER: KOA コーア; POWERRATING: 100m; MOUNTINGFORMSMD: SMD; COMP: PRT_8; ADSMODELNAME: s_RK73B1JTTD103J@@; FNLEADFREETHET1GT2GMCTH1: N_N_N; VAL3: RK73B1JTTD103J; VAL2: 100mW,±5%; OUMECLASSIFICATION: 表面実装用固定抵抗器; OUMEMAKERKATAMEI: RK73B1JTTD103J@@; INSTANCENAME: INS6535
R22 = R: PARTNAME: Chip1608_GS_1; ORIGINALSYMBOLORIGIN: (0,0); TIME: 16:40:04; UPDATEUSER: t5459927; SAVECOUNT: 1; QUADMODEL: RES_10K; FUNCTION: R_R.Normal_package; CDMASTERCADCELG: KC0133; MAKER: KOA; RESISTANCETOLER: J; SIZECODESMD: 1608; OUMEMAKER: KOA コーア; POWERRATING: 100m; MOUNTINGFORMSMD: SMD; COMP: PRT_8; ADSMODELNAME: s_RK73B1JTTD103J@@; FNLEADFREETHET1GT2GMCTH1: N_N_N; VAL3: RK73B1JTTD103J; VAL2: 100mW,±5%; OUMECLASSIFICATION: 表面実装用固定抵抗器; OUMEMAKERKATAMEI: RK73B1JTTD103J@@; INSTANCENAME: INS6635
R23 = R: PARTNAME: Chip3216_GS_1; ORIGINALSYMBOLORIGIN: (0,0); TIME: 16:40:04; UPDATEUSER: t5459927; SAVECOUNT: 1; QUADMODEL: RES_3.3; FUNCTION: R_R.Normal_package; CDMASTERCADCELG: KC0014; MAKER: VISHAY; RESISTANCETOLER: J; SIZECODESMD: 3216; OUMEMAKER: NAE パナソニックエレクトロニックデバイス; POWERRATING: 250m; MOUNTINGFORMSMD: SMD; NOMINALRESISTAN: 3.3; COMP: PRT_5; ADSMODELNAME: s_ERJ8GEYJ3R3V; FNLEADFREETHET1GT2GMCTH1: N_N_N; VAL3: CRCW12063R01FKEAHP; VAL2: 500mW,±1%; OUMECLASSIFICATION: 表面実装用固定抵抗器; OUMEMAKERKATAMEI: ERJ8GEYJ3R3V; INSTANCENAME: INS6645
R24 = R: PARTNAME: Chip3216_GS_1; ORIGINALSYMBOLORIGIN: (0,0); TIME: 16:40:04; UPDATEUSER: t5459927; SAVECOUNT: 1; QUADMODEL: RES_3.3; FUNCTION: R_R.Normal_package; CDMASTERCADCELG: KC0014; MAKER: VISHAY; RESISTANCETOLER: J; SIZECODESMD: 3216; OUMEMAKER: NAE パナソニックエレクトロニックデバイス; POWERRATING: 250m; MOUNTINGFORMSMD: SMD; NOMINALRESISTAN: 3.3; COMP: PRT_5; ADSMODELNAME: s_ERJ8GEYJ3R3V; FNLEADFREETHET1GT2GMCTH1: N_N_N; VAL3: CRCW12063R01FKEAHP; VAL2: 500mW,±1%; OUMECLASSIFICATION: 表面実装用固定抵抗器; OUMEMAKERKATAMEI: ERJ8GEYJ3R3V; INSTANCENAME: INS6575
R25 = R: PARTNAME: Chip1608_GS_1; ORIGINALSYMBOLORIGIN: (0,0); TIME: 16:40:04; UPDATEUSER: t5459927; SAVECOUNT: 1; QUADMODEL: RES_10K; FUNCTION: R_R.Normal_package; CDMASTERCADCELG: KC0133; MAKER: KOA; RESISTANCETOLER: J; SIZECODESMD: 1608; OUMEMAKER: KOA コーア; POWERRATING: 100m; MOUNTINGFORMSMD: SMD; COMP: PRT_8; ADSMODELNAME: s_RK73B1JTTD103J@@; FNLEADFREETHET1GT2GMCTH1: N_N_N; VAL3: RK73B1JTTD103J; VAL2: 100mW,±5%; OUMECLASSIFICATION: 表面実装用固定抵抗器; OUMEMAKERKATAMEI: RK73B1JTTD103J@@; INSTANCENAME: INS6625
R76 = R: PARTNAME: Chip6432_GS; ORIGINALSYMBOLORIGIN: (0,0); TIME: 16:40:04; UPDATEUSER: t5459927; SAVECOUNT: 1; COMPONENTNAME: R_R.Normal_package; SIZECODESMD: 3216; ADSMODELNAME: s_RK73H2BTTD1003F@@; MOUNTINGFORMSMD: SMD; MAKER: PANASONIC; VAL2: 250mW,±5%; PMPRODUCTSTYPEG: DA; COMP: PRT_5; ADSCOMPONENTNAME: R_3216; INSTANCENAME: INS6097
R77 = R: PARTNAME: MOS3C_KO; ORIGINALSYMBOLORIGIN: (0,0); TIME: 16:40:04; UPDATEUSER: t5459927; SAVECOUNT: 1; NOTMOUNT: NOT MOUNT; RESISTANCETOLER: J; COMPONENTNAME: R_R.Normal_package; FNLEADFREETHET1GT2GMCTH1: N_N_N; NOMINALRESISTAN: 100; POWERRATING: 3; OUMEMAKER: KOA コーア; OUMECLASSIFICATION: 酸化金属皮膜固定抵抗器; VAL3: PR03000201001JAC00; MOUNTINGFORMSMD: DIP; MAKER: VISHAY; OUMEMAKERKATAMEI: MOS3CT521A101J@@; PMPRODUCTSTYPEG: HEV; CDMASTERCADCELG: AXK0015; QUADMODEL: RES_100; COMP: PRT_54; INSTANCENAME: INS6107
R78 = R: PARTNAME: MOS3C_KO; ORIGINALSYMBOLORIGIN: (0,0); TIME: 16:40:04; UPDATEUSER: t5459927; SAVECOUNT: 1; QUADMODEL: RES_100; FUNCTION: R_R.Normal_package; CDMASTERCADCELG: AXK0015; MAKER: VISHAY; RESISTANCETOLER: J; OUMEMAKER: KOA コーア; POWERRATING: 3; MOUNTINGFORMSMD: DIP; NOMINALRESISTAN: 100; COMP: PRT_54; PMPRODUCTSTYPEG: HEV; FNLEADFREETHET1GT2GMCTH1: N_N_N; VAL3: PR03000201001JAC00; OUMECLASSIFICATION: 酸化金属皮膜固定抵抗器; NOTMOUNT: NOT MOUNT; OUMEMAKERKATAMEI: MOS3CT521A101J@@; INSTANCENAME: INS6133
R105 = R: PARTNAME: Chip6432_GS; ORIGINALSYMBOLORIGIN: (0,0); TIME: 16:40:04; UPDATEUSER: t5459927; SAVECOUNT: 1; COMPONENTNAME: R_R.Normal_package; SIZECODESMD: 3216; ADSMODELNAME: s_RK73H2BTTD1003F@@; MOUNTINGFORMSMD: SMD; MAKER: PANASONIC; VAL2: 250mW,±5%; PMPRODUCTSTYPEG: DA; COMP: PRT_5; ADSCOMPONENTNAME: R_3216; INSTANCENAME: INS6047
R106 = R: PARTNAME: MOS3C_KO; ORIGINALSYMBOLORIGIN: (0,0); TIME: 16:40:04; UPDATEUSER: t5459927; SAVECOUNT: 1; NOTMOUNT: NOT MOUNT; RESISTANCETOLER: J; COMPONENTNAME: R_R.Normal_package; FNLEADFREETHET1GT2GMCTH1: N_N_N; NOMINALRESISTAN: 100; POWERRATING: 3; OUMEMAKER: KOA コーア; OUMECLASSIFICATION: 酸化金属皮膜固定抵抗器; VAL3: PR03000201001JAC00; MOUNTINGFORMSMD: DIP; MAKER: VISHAY; OUMEMAKERKATAMEI: MOS3CT521A101J@@; PMPRODUCTSTYPEG: HEV; CDMASTERCADCELG: AXK0015; QUADMODEL: RES_100; COMP: PRT_54; INSTANCENAME: INS6057
R107 = R: PARTNAME: MOS3C_KO; ORIGINALSYMBOLORIGIN: (0,0); TIME: 16:40:04; UPDATEUSER: t5459927; SAVECOUNT: 1; QUADMODEL: RES_100; FUNCTION: R_R.Normal_package; CDMASTERCADCELG: AXK0015; MAKER: VISHAY; RESISTANCETOLER: J; OUMEMAKER: KOA コーア; POWERRATING: 3; MOUNTINGFORMSMD: DIP; NOMINALRESISTAN: 100; COMP: PRT_54; PMPRODUCTSTYPEG: HEV; FNLEADFREETHET1GT2GMCTH1: N_N_N; VAL3: PR03000201001JAC00; VAL2: 3W,±5%; OUMECLASSIFICATION: 酸化金属皮膜固定抵抗器; OUMEMAKERKATAMEI: MOS3CT521A101J@@; INSTANCENAME: INS6069
R118 = R: PARTNAME: Chip6432_GS; ORIGINALSYMBOLORIGIN: (0,0); TIME: 16:40:04; UPDATEUSER: t5459927; SAVECOUNT: 1; NOTMOUNT: NOT MOUNT; COMPONENTNAME: R_R.Normal_package; SIZECODESMD: 6432; ADSMODELNAME: s_RK73H2BTTD1003F@@; MOUNTINGFORMSMD: SMD; MAKER: KOA; VAL2: 1W,・}%; PMPRODUCTSTYPEG: DA; COMP: PRT_5; ADSCOMPONENTNAME: R_3216; CHIPSIZE: 3216; INSTANCENAME: INS17040861
R119 = R: PARTNAME: Chip6432_GS; ORIGINALSYMBOLORIGIN: (0,0); TIME: 16:40:04; UPDATEUSER: t5459927; SAVECOUNT: 1; NOTMOUNT: NOT MOUNT; COMPONENTNAME: R_R.Normal_package; SIZECODESMD: 6432; ADSMODELNAME: s_RK73H2BTTD1003F@@; MOUNTINGFORMSMD: SMD; MAKER: KOA; VAL2: 1W,・}%; PMPRODUCTSTYPEG: DA; COMP: PRT_5; ADSCOMPONENTNAME: R_3216; CHIPSIZE: 3216; INSTANCENAME: INS17040874
R124 = R: PARTNAME: Chip1608_GS_1; ORIGINALSYMBOLORIGIN: (0,0); TIME: 16:40:04; UPDATEUSER: t5459927; QUADMODEL: RES_1; FUNCTION: R_R.Normal_package; CDMASTERCADCELG: KC0008; MAKER: PANASONIC; RESISTANCETOLER: J; SIZECODESMD: 1608; OUMEMAKER: NAE パナソニックエレクトロニックデバイス; POWERRATING: 63m; MOUNTINGFORMSMD: SMD; COMP: PRT_8; ADSMODELNAME: s_ERJ3GEYJ1R0V; PMPRODUCTSTYPEG: PC1; FNLEADFREETHET1GT2GMCTH1: 2_1_N; VAL3: ERJ-3GEYJ1R0V; VAL2: 100mW,±5%; OUMECLASSIFICATION: 表面実装用固定抵抗器; OUMEMAKERKATAMEI: ERJ3GEYJ1R0V; INSTANCENAME: INS6009
R125 = R: PARTNAME: Chip1608_GS_1; ORIGINALSYMBOLORIGIN: (0,0); TIME: 16:40:04; UPDATEUSER: t5459927; QUADMODEL: RES_1; FUNCTION: R_R.Normal_package; CDMASTERCADCELG: KC0008; MAKER: PANASONIC; RESISTANCETOLER: J; SIZECODESMD: 1608; OUMEMAKER: NAE パナソニックエレクトロニックデバイス; POWERRATING: 63m; MOUNTINGFORMSMD: SMD; COMP: PRT_8; ADSMODELNAME: s_ERJ3GEYJ1R0V; PMPRODUCTSTYPEG: PC1; FNLEADFREETHET1GT2GMCTH1: 2_1_N; VAL3: ERJ-3GEYJ1R0V; VAL2: 100mW,±5%; OUMECLASSIFICATION: 表面実装用固定抵抗器; OUMEMAKERKATAMEI: ERJ3GEYJ1R0V; INSTANCENAME: INS6147
R128 = R: PARTNAME: MOS3C_KO; ORIGINALSYMBOLORIGIN: (0,0); TIME: 16:40:04; UPDATEUSER: t5459927; SAVECOUNT: 1; QUADMODEL: RES_100; FUNCTION: R_R.Normal_package; CDMASTERCADCELG: AXK0015; MAKER: VISHAY; RESISTANCETOLER: J; OUMEMAKER: KOA コーア; POWERRATING: 3; MOUNTINGFORMSMD: DIP; NOMINALRESISTAN: 100; COMP: PRT_54; PMPRODUCTSTYPEG: HEV; FNLEADFREETHET1GT2GMCTH1: N_N_N; VAL3: PR03000201001JAC00; VAL2: 3W,±5%; OUMECLASSIFICATION: 酸化金属皮膜固定抵抗器; OUMEMAKERKATAMEI: MOS3CT521A101J@@; INSTANCENAME: INS6119
R129 = R: PARTNAME: MOS3C_KO; ORIGINALSYMBOLORIGIN: (0,0); TIME: 16:40:04; UPDATEUSER: t5459927; SAVECOUNT: 1; QUADMODEL: RES_100; FUNCTION: R_R.Normal_package; CDMASTERCADCELG: AXK0015; MAKER: VISHAY; RESISTANCETOLER: J; OUMEMAKER: KOA コーア; POWERRATING: 3; MOUNTINGFORMSMD: DIP; NOMINALRESISTAN: 100; COMP: PRT_54; PMPRODUCTSTYPEG: HEV; FNLEADFREETHET1GT2GMCTH1: N_N_N; VAL3: PR03000201001JAC00; OUMECLASSIFICATION: 酸化金属皮膜固定抵抗器; NOTMOUNT: NOT MOUNT; OUMEMAKERKATAMEI: MOS3CT521A101J@@; INSTANCENAME: INS6083
R140 = R: PARTNAME: Chip6432_GS; ORIGINALSYMBOLORIGIN: (0,0); TIME: 16:40:04; UPDATEUSER: t5459927; SAVECOUNT: 1; NOTMOUNT: NOT MOUNT; COMPONENTNAME: R_R.Normal_package; SIZECODESMD: 6432; ADSMODELNAME: s_RK73H2BTTD1003F@@; MOUNTINGFORMSMD: SMD; MAKER: KOA; VAL2: 1W,・}%; PMPRODUCTSTYPEG: DA; COMP: PRT_5; ADSCOMPONENTNAME: R_3216; CHIPSIZE: 3216; INSTANCENAME: INS17041940
R141 = R: PARTNAME: Chip6432_GS; ORIGINALSYMBOLORIGIN: (0,0); TIME: 16:40:04; UPDATEUSER: t5459927; SAVECOUNT: 1; NOTMOUNT: NOT MOUNT; COMPONENTNAME: R_R.Normal_package; SIZECODESMD: 6432; ADSMODELNAME: s_RK73H2BTTD1003F@@; MOUNTINGFORMSMD: SMD; MAKER: KOA; VAL2: 1W,・}%; PMPRODUCTSTYPEG: DA; COMP: PRT_5; ADSCOMPONENTNAME: R_3216; CHIPSIZE: 3216; INSTANCENAME: INS17040848
R199 = R: PARTNAME: Chip6432_GS; ORIGINALSYMBOLORIGIN: (0,0); TIME: 16:40:04; UPDATEUSER: t5459927; SAVECOUNT: 1; PMPRODUCTSTYPEG: HEV; COMP: PRT_43; CHIPSIZE: 6432; FUNCTION: R_R.Normal_package; MOUNTINGFORMSMD: DIP; VAL3: CRCW2512680RFKEG; VAL2: 1W,±5%; MAKER: VISHAY; INSTANCENAME: INS6245
R200 = R: PARTNAME: Chip6432_GS; ORIGINALSYMBOLORIGIN: (0,0); TIME: 16:40:04; UPDATEUSER: t5459927; SAVECOUNT: 1; PMPRODUCTSTYPEG: HEV; COMP: PRT_43; CHIPSIZE: 6432; FUNCTION: R_R.Normal_package; MOUNTINGFORMSMD: DIP; VAL3: CRCW2512680RFKEG; VAL2: 1W,±5%; MAKER: VISHAY; INSTANCENAME: INS6257
R201 = R: PARTNAME: Chip6432_GS; ORIGINALSYMBOLORIGIN: (0,0); TIME: 16:40:04; UPDATEUSER: t5459927; SAVECOUNT: 1; PMPRODUCTSTYPEG: HEV; COMP: PRT_43; CHIPSIZE: 6432; FUNCTION: R_R.Normal_package; NOTMOUNT: NOT MOUNT; MOUNTINGFORMSMD: DIP; VAL3: CRCW2512680RFKEG; VAL2: 1W,±5%; MAKER: VISHAY; INSTANCENAME: INS6271
R212 = R: PARTNAME: Chip3216_GS_1; ORIGINALSYMBOLORIGIN: (0,0); TIME: 16:40:04; UPDATEUSER: t5459927; SAVECOUNT: 1; QUADMODEL: RES_3.3; FUNCTION: R_R.Normal_package; CDMASTERCADCELG: KC0014; MAKER: VISHAY; RESISTANCETOLER: J; SIZECODESMD: 3216; OUMEMAKER: NAE パナソニックエレクトロニックデバイス; POWERRATING: 250m; MOUNTINGFORMSMD: SMD; NOMINALRESISTAN: 3.3; COMP: PRT_5; ADSMODELNAME: s_ERJ8GEYJ3R3V; FNLEADFREETHET1GT2GMCTH1: N_N_N; VAL3: CRCW12063R01FKEAHP; VAL2: 500mW,±1%; OUMECLASSIFICATION: 表面実装用固定抵抗器; OUMEMAKERKATAMEI: ERJ8GEYJ3R3V; INSTANCENAME: INS6515
R213 = R: PARTNAME: Chip3216_GS_1; ORIGINALSYMBOLORIGIN: (0,0); TIME: 16:40:04; UPDATEUSER: t5459927; SAVECOUNT: 1; QUADMODEL: RES_3.3; FUNCTION: R_R.Normal_package; CDMASTERCADCELG: KC0014; MAKER: VISHAY; RESISTANCETOLER: J; SIZECODESMD: 3216; OUMEMAKER: NAE パナソニックエレクトロニックデバイス; POWERRATING: 250m; MOUNTINGFORMSMD: SMD; NOMINALRESISTAN: 3.3; COMP: PRT_5; ADSMODELNAME: s_ERJ8GEYJ3R3V; FNLEADFREETHET1GT2GMCTH1: N_N_N; VAL3: CRCW12063R01FKEAHP; VAL2: 500mW,±1%; OUMECLASSIFICATION: 表面実装用固定抵抗器; OUMEMAKERKATAMEI: ERJ8GEYJ3R3V; INSTANCENAME: INS6485
R214 = R: PARTNAME: Chip3216_GS_1; ORIGINALSYMBOLORIGIN: (0,0); TIME: 16:40:04; UPDATEUSER: t5459927; SAVECOUNT: 1; QUADMODEL: RES_3.3; FUNCTION: R_R.Normal_package; CDMASTERCADCELG: KC0014; MAKER: VISHAY; RESISTANCETOLER: J; SIZECODESMD: 3216; OUMEMAKER: NAE パナソニックエレクトロニックデバイス; POWERRATING: 250m; MOUNTINGFORMSMD: SMD; NOMINALRESISTAN: 3.3; COMP: PRT_5; ADSMODELNAME: s_ERJ8GEYJ3R3V; FNLEADFREETHET1GT2GMCTH1: N_N_N; VAL3: CRCW12063R01FKEAHP; VAL2: 500mW,±1%; OUMECLASSIFICATION: 表面実装用固定抵抗器; OUMEMAKERKATAMEI: ERJ8GEYJ3R3V; INSTANCENAME: INS6655
R215 = R: PARTNAME: Chip3216_GS_1; ORIGINALSYMBOLORIGIN: (0,0); TIME: 16:40:04; UPDATEUSER: t5459927; SAVECOUNT: 1; QUADMODEL: RES_3.3; FUNCTION: R_R.Normal_package; CDMASTERCADCELG: KC0014; MAKER: VISHAY; RESISTANCETOLER: J; SIZECODESMD: 3216; OUMEMAKER: NAE パナソニックエレクトロニックデバイス; POWERRATING: 250m; MOUNTINGFORMSMD: SMD; NOMINALRESISTAN: 3.3; COMP: PRT_5; ADSMODELNAME: s_ERJ8GEYJ3R3V; FNLEADFREETHET1GT2GMCTH1: N_N_N; VAL3: CRCW12063R01FKEAHP; VAL2: 500mW,±1%; OUMECLASSIFICATION: 表面実装用固定抵抗器; OUMEMAKERKATAMEI: ERJ8GEYJ3R3V; INSTANCENAME: INS6585
T5 T6 = T3_8: PARTNAME: AN0545_GS; UPDATEUSER: t5459927; UPDATETIME: 11:21:50; SAVECOUNT: 4; TIME: 16:40:06; SAVEAREA0: -24785,-29107,44415,-156; ORIGINALSYMBOLORIGIN: (-7620,0)
TP17 = TP: PARTNAME: HK-2_M8; UPDATEUSER: t5459927; UPDATETIME: 16:40:05; SAVECOUNT: 1; SAVEAREA0: -242,-92,12810,7836; ORIGINALSYMBOLORIGIN: (0,0); COMP: PRT_44; FUNCTION: TP_TP.Normal_package; MAKER: MAC8; INSTANCENAME: INS6701
TP18 = TP: PARTNAME: HK-2_M8; UPDATEUSER: t5459927; UPDATETIME: 16:40:05; SAVECOUNT: 1; SAVEAREA0: -242,-92,12810,7836; ORIGINALSYMBOLORIGIN: (0,0); COMP: PRT_44; FUNCTION: TP_TP.Normal_package; MAKER: MAC8; INSTANCENAME: INS6725
TP19 = TP: PARTNAME: HK-2_M8; UPDATEUSER: t5459927; UPDATETIME: 16:40:05; SAVECOUNT: 1; SAVEAREA0: -242,-92,12810,7836; ORIGINALSYMBOLORIGIN: (0,0); COMPONENTNAME: TP_TP.Normal_package; ID: Q13-G; MAKER: MAC8; COMP: PRT_44; INSTANCENAME: INS6749
TP20 = TP: PARTNAME: HK-2_M8; UPDATEUSER: t5459927; UPDATETIME: 16:40:05; SAVECOUNT: 1; SAVEAREA0: -242,-92,12810,7836; ORIGINALSYMBOLORIGIN: (0,0); COMPONENTNAME: TP_TP.Normal_package; ID: Q9-G; MAKER: MAC8; COMP: PRT_44; INSTANCENAME: INS6717
TP21 = TP: PARTNAME: HK-2_M8; UPDATEUSER: t5459927; UPDATETIME: 16:40:05; SAVECOUNT: 1; SAVEAREA0: -242,-92,12810,7836; ORIGINALSYMBOLORIGIN: (0,0); COMPONENTNAME: TP_TP.Normal_package; ID: Q11-G; MAKER: MAC8; COMP: PRT_44; INSTANCENAME: INS6685
TP22 = TP: PARTNAME: HK-2_M8; UPDATEUSER: t5459927; UPDATETIME: 16:40:05; SAVECOUNT: 1; SAVEAREA0: -242,-92,12810,7836; ORIGINALSYMBOLORIGIN: (0,0); COMPONENTNAME: TP_TP.Normal_package; ID: Q7-G; MAKER: MAC8; COMP: PRT_44; INSTANCENAME: INS6709
TP24 = TP: PARTNAME: HK-2_M8; UPDATEUSER: t5459927; UPDATETIME: 16:40:05; SAVECOUNT: 1; SAVEAREA0: -242,-92,12810,7836; ORIGINALSYMBOLORIGIN: (0,0); COMPONENTNAME: TP_TP.Normal_package; ID: OUTF; MAKER: MAC8; COMP: PRT_44; INSTANCENAME: INS6765
TP25 = TP: PARTNAME: HK-2_M8; UPDATEUSER: t5459927; UPDATETIME: 16:40:05; SAVECOUNT: 1; SAVEAREA0: -242,-92,12810,7836; ORIGINALSYMBOLORIGIN: (0,0); COMPONENTNAME: TP_TP.Normal_package; ID: OUTE; MAKER: MAC8; COMP: PRT_44; INSTANCENAME: INS6773
TP29 = TP: PARTNAME: HK-2_M8; UPDATEUSER: t5459927; UPDATETIME: 16:40:05; SAVECOUNT: 1; SAVEAREA0: -242,-92,12810,7836; ORIGINALSYMBOLORIGIN: (0,0); COMP: PRT_44; FUNCTION: TP_TP.Normal_package; MAKER: MAC8; INSTANCENAME: INS6733
TP30 = TP: PARTNAME: HK-2_M8; UPDATEUSER: t5459927; UPDATETIME: 16:40:05; SAVECOUNT: 1; SAVEAREA0: -242,-92,12810,7836; ORIGINALSYMBOLORIGIN: (0,0); COMP: PRT_44; FUNCTION: TP_TP.Normal_package; MAKER: MAC8; INSTANCENAME: INS6741
TP41 = TP: PARTNAME: LC-22_GS; UPDATEUSER: t5459927; UPDATETIME: 16:40:05; SAVECOUNT: 1; SAVEAREA0: -242,-92,12810,7836; ORIGINALSYMBOLORIGIN: (0,0); COMPONENTNAME: TP_TP.Normal_package; ID: LGND; MAKER: MAC8; COMP: PRT_34; INSTANCENAME: INS6797
U?#5 = WAKU_DEF100: PLOTTIME: HH:MM; SAVEAREA0: 168739,-66042,466246,90057; TIME: 14:30:25; UPDATEUSER: t5459927; UPDATETIME: 15:16:57; SAVECOUNT: 5; OriginalSymbolOrigin: (10160,284480)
